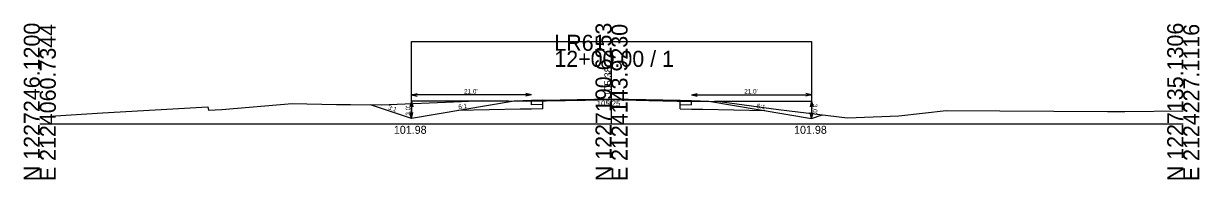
# Model space of a CAD drawing. Extents: x 2126751 to 2128979, y 1225108 to 1234639.
# Drawn here: x 2127773.8 to 2127979.4, y 1227107.5 to 1227134.8 of the extents above; entities that cross this region are included whole.
import ezdxf

# ---------------------------------------------------------------- set-up
doc = ezdxf.new("R2010")
doc.units = 0
for name, color, linetype in [('XS_CELL', 7, 'Continuous'), ('XS_M_DITCH', 7, 'Continuous'), ('XS_P_FINISHED_GRADE', 7, 'Continuous'), ('XS_P_FINISHED_GRADE_ELEV_TX', 7, 'Continuous'), ('XS_P_SUBGRADE_GRANULAR', 7, 'Continuous'), ('XS_P_SUBGRADE_LEVELING', 7, 'Continuous'), ('XS_P_SUBGRADE_PAVEMENT', 7, 'Continuous'), ('XS_P_TX_CLEARZONE', 7, 'Continuous'), ('XS_P_TX_DCH', 7, 'Continuous'), ('XS_P_TX_FS_BS', 7, 'Continuous'), ('XS_X_GROUND', 7, 'Continuous'), ('XS_X_GROUND_TX', 7, 'Continuous')]:
    doc.layers.add(name, color=color, linetype=linetype)

msp = doc.modelspace()

# ---------------------------------------------------------------- linework, layer by layer
at = {"layer": 'XS_CELL'}
for p, q in [((2127876.61, 1227117.21), (2127876.61, 1227129.99)), ((2127776.61, 1227117.21), (2127876.61, 1227117.21)), ((2127876.61, 1227117.21), (2127976.61, 1227117.21))]:
    msp.add_line(p, q, dxfattribs=at)
at = {"layer": 'XS_M_DITCH'}
for p, q in [((2127841.61, 1227118.19), (2127841.61, 1227131.59)), ((2127841.61, 1227131.59), (2127911.61, 1227131.59)), ((2127911.61, 1227131.59), (2127911.61, 1227118.19))]:
    msp.add_line(p, q, dxfattribs=at)
at = {"layer": 'XS_P_FINISHED_GRADE'}
for p, q in [((2127841.61, 1227118.19), (2127834.45, 1227120.58)), ((2127859.61, 1227121.19), (2127841.61, 1227118.19)), ((2127862.61, 1227121.31), (2127859.61, 1227121.19)), ((2127864.61, 1227121.35), (2127862.61, 1227121.31)), ((2127864.61, 1227121.35), (2127876.61, 1227121.59)), ((2127876.61, 1227121.59), (2127888.61, 1227121.35)), ((2127888.61, 1227121.35), (2127890.61, 1227121.31)), ((2127890.61, 1227121.31), (2127893.61, 1227121.19)), ((2127893.61, 1227121.19), (2127911.61, 1227118.19)), ((2127911.61, 1227118.19), (2127913.47, 1227118.81))]:
    msp.add_line(p, q, dxfattribs=at)
at = {"layer": 'XS_P_SUBGRADE_GRANULAR'}
for p, q in [((2127864.61, 1227119.85), (2127864.61, 1227120.6)), ((2127888.61, 1227119.85), (2127888.61, 1227120.6)), ((2127860.61, 1227119.77), (2127849.79, 1227119.55)), ((2127862.61, 1227119.81), (2127860.61, 1227119.77)), ((2127864.61, 1227119.85), (2127862.61, 1227119.81)), ((2127888.61, 1227119.85), (2127890.61, 1227119.81)), ((2127890.61, 1227119.81), (2127892.61, 1227119.77)), ((2127892.61, 1227119.77), (2127903.43, 1227119.55))]:
    msp.add_line(p, q, dxfattribs=at)
at = {"layer": 'XS_P_SUBGRADE_LEVELING'}
for p, q in [((2127864.61, 1227121.23), (2127871.98, 1227121.37)), ((2127864.61, 1227121.35), (2127864.61, 1227121.23)), ((2127871.98, 1227121.37), (2127876.43, 1227121.47)), ((2127876.43, 1227121.47), (2127883.15, 1227121.31)), ((2127883.15, 1227121.31), (2127888.61, 1227121.17)), ((2127888.61, 1227121.35), (2127888.61, 1227121.17))]:
    msp.add_line(p, q, dxfattribs=at)
at = {"layer": 'XS_P_SUBGRADE_PAVEMENT'}
for p, q in [((2127862.61, 1227120.56), (2127862.61, 1227121.31)), ((2127864.61, 1227120.6), (2127862.61, 1227120.56)), ((2127864.61, 1227120.6), (2127864.61, 1227121.23)), ((2127888.61, 1227120.6), (2127888.61, 1227121.17)), ((2127888.61, 1227120.6), (2127890.61, 1227120.56)), ((2127890.61, 1227120.56), (2127890.61, 1227121.31))]:
    msp.add_line(p, q, dxfattribs=at)
at = {"layer": 'XS_P_TX_CLEARZONE'}
for p, q in [((2127841.61, 1227122.31), (2127842.61, 1227122.56)), ((2127862.61, 1227122.31), (2127861.61, 1227122.56)), ((2127890.61, 1227122.31), (2127891.61, 1227122.56)), ((2127911.61, 1227122.31), (2127910.61, 1227122.56)), ((2127841.61, 1227121.19), (2127841.36, 1227120.19)), ((2127841.61, 1227122.31), (2127842.61, 1227122.06)), ((2127862.61, 1227122.31), (2127841.61, 1227122.31)), ((2127841.61, 1227121.19), (2127841.86, 1227120.19)), ((2127841.61, 1227121.19), (2127841.61, 1227118.19)), ((2127858.61, 1227121.19), (2127841.61, 1227121.19)), ((2127862.61, 1227122.31), (2127861.61, 1227122.06)), ((2127890.61, 1227122.31), (2127891.61, 1227122.06)), ((2127890.61, 1227122.31), (2127911.61, 1227122.31)), ((2127894.61, 1227121.19), (2127911.61, 1227121.19)), ((2127911.61, 1227122.31), (2127910.61, 1227122.06)), ((2127911.61, 1227121.19), (2127911.36, 1227120.19)), ((2127911.61, 1227121.19), (2127911.61, 1227118.19)), ((2127911.61, 1227121.19), (2127911.86, 1227120.19)), ((2127841.61, 1227118.19), (2127841.36, 1227119.19)), ((2127841.61, 1227118.19), (2127841.86, 1227119.19)), ((2127911.61, 1227118.19), (2127911.36, 1227119.19)), ((2127911.61, 1227118.19), (2127911.86, 1227119.19))]:
    msp.add_line(p, q, dxfattribs=at)
at = {"layer": 'XS_X_GROUND'}
for p, q in [((2127808.46, 1227119.76), (2127820.75, 1227120.78)), ((2127820.75, 1227120.78), (2127828.49, 1227120.62)), ((2127828.49, 1227120.62), (2127830.96, 1227120.6)), ((2127830.96, 1227120.6), (2127836.33, 1227120.56)), ((2127836.33, 1227120.56), (2127850.37, 1227121.16)), ((2127850.37, 1227121.16), (2127854.13, 1227121.33)), ((2127854.13, 1227121.33), (2127856.97, 1227121.27)), ((2127856.97, 1227121.27), (2127861.75, 1227121.17)), ((2127861.75, 1227121.17), (2127871.98, 1227121.37)), ((2127871.98, 1227121.37), (2127876.43, 1227121.47)), ((2127876.43, 1227121.47), (2127883.15, 1227121.31)), ((2127883.15, 1227121.31), (2127890.56, 1227121.12)), ((2127890.56, 1227121.12), (2127895.11, 1227121.22)), ((2127895.11, 1227121.22), (2127905.81, 1227119.72)), ((2127776.61, 1227118.47), (2127787.57, 1227119.18)), ((2127787.57, 1227119.18), (2127806.01, 1227120.18)), ((2127806.01, 1227120.18), (2127806.13, 1227119.62)), ((2127806.13, 1227119.62), (2127808.46, 1227119.76)), ((2127905.81, 1227119.72), (2127917.89, 1227118.29)), ((2127917.89, 1227118.29), (2127926.87, 1227118.62)), ((2127926.87, 1227118.62), (2127935.12, 1227119.56)), ((2127935.12, 1227119.56), (2127963.36, 1227119.4)), ((2127963.36, 1227119.4), (2127964.86, 1227119.41)), ((2127964.86, 1227119.41), (2127966.41, 1227119.39)), ((2127966.41, 1227119.39), (2127976.61, 1227119.52))]:
    msp.add_line(p, q, dxfattribs=at)

# ---------------------------------------------------------------- texts
at = {"layer": 'XS_CELL'}
for s, p in [('N 1227246.1200', (2127776.61, 1227107.21)), ('E 2124060.7344', (2127779.41, 1227107.21)), ('N 1227190.6253', (2127876.61, 1227107.21)), ('E 2124143.9230', (2127879.41, 1227107.21)), ('N 1227135.1306', (2127976.61, 1227107.21)), ('E 2124227.1116', (2127979.41, 1227107.21))]:
    msp.add_text(s, height=2.8, rotation=90, dxfattribs=at).set_placement(p)
for s, p in [('LR61', (2127866.61, 1227129.99)), ('12+00.00 / 1', (2127866.61, 1227127.19))]:
    msp.add_text(s, height=2.8, dxfattribs=at).set_placement(p)
at = {"layer": 'XS_P_FINISHED_GRADE_ELEV_TX'}
msp.add_text(' 105.38', height=1.25, rotation=90, dxfattribs=at).set_placement((2127876.61, 1227121.59))
at = {"layer": 'XS_P_TX_CLEARZONE'}
for p in [(2127850.82, 1227122.51), (2127899.82, 1227122.51)]:
    msp.add_text("21.0'", height=0.8, dxfattribs=at).set_placement(p)
for rotation, p in [(270, (2127911.81, 1227120.72)), (90, (2127841.41, 1227118.66))]:
    msp.add_text("3.0'", height=0.8, rotation=rotation, dxfattribs=at).set_placement(p)
at = {"layer": 'XS_P_TX_DCH'}
for p in [(2127838.54, 1227115.49), (2127908.54, 1227115.49)]:
    msp.add_text('101.98', height=1.4, dxfattribs=at).set_placement(p)
at = {"layer": 'XS_P_TX_FS_BS'}
for s, rotation, p in [('3:1', 341.5651, (2127837.45, 1227119.79)), ('6:1', 9.4623, (2127849.89, 1227119.77)), ('6:1', 350.5377, (2127901.95, 1227120))]:
    msp.add_text(s, height=0.8, rotation=rotation, dxfattribs=at).set_placement(p)
at = {"layer": 'XS_X_GROUND_TX'}
msp.add_text('105.25', height=1, dxfattribs=at).set_placement((2127874.05, 1227120.3))

doc.saveas('drawing.dxf')
